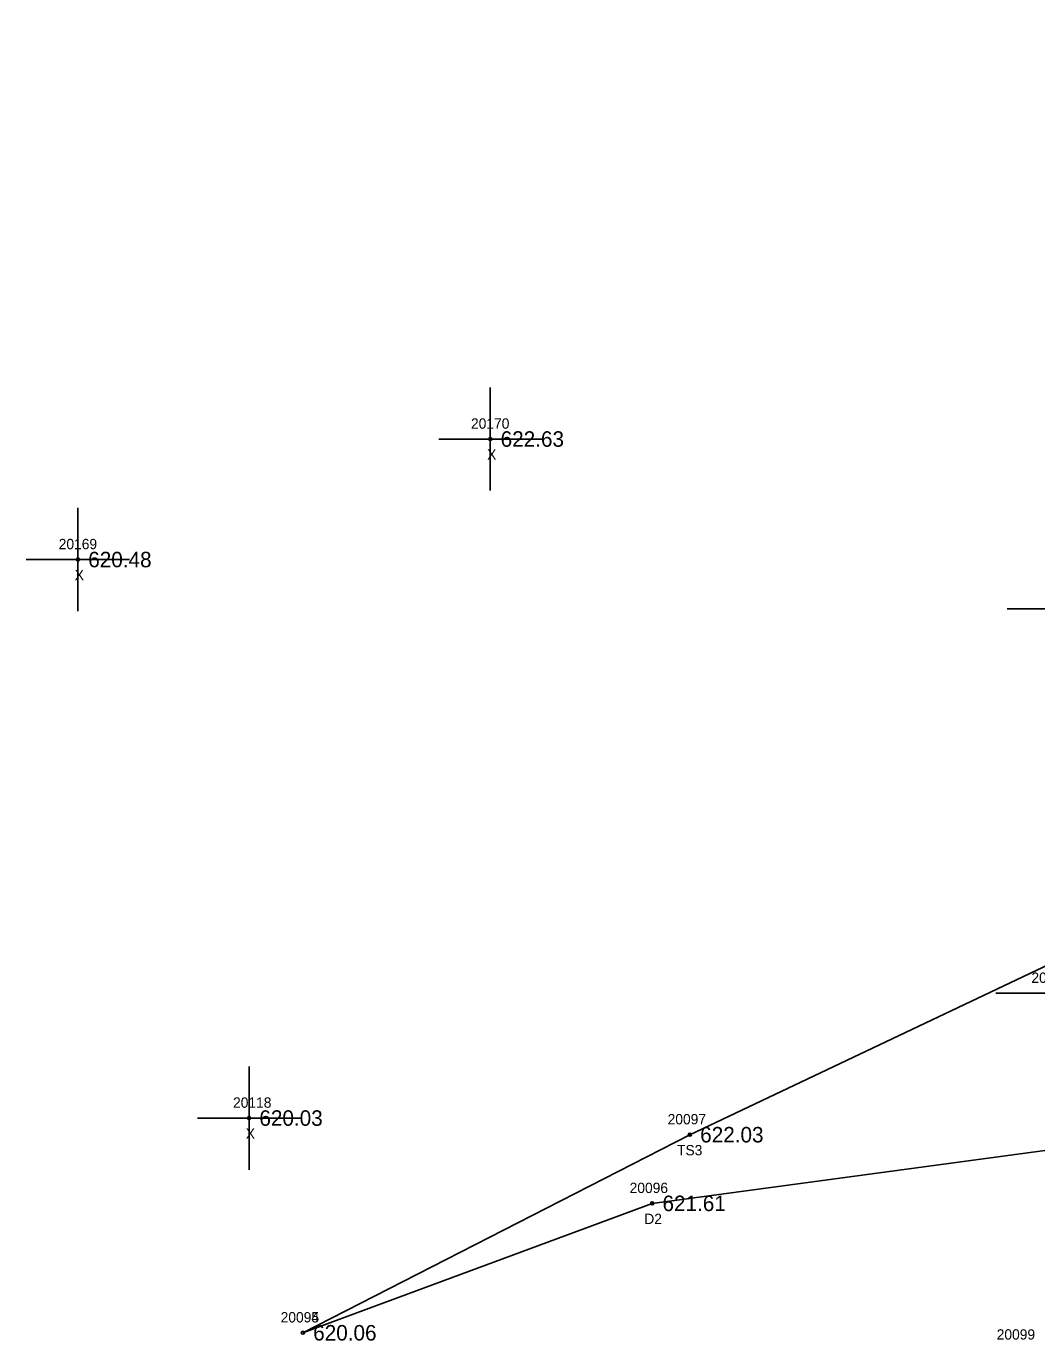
# Model space of a CAD drawing. Extents: x 1695443 to 1696344, y 1087542 to 1090645.
# Drawn here: x 1695784.6 to 1695882.4, y 1088055.7 to 1088182.9 of the extents above; entities that cross this region are included whole.
import ezdxf

# ---------------------------------------------------------------- set-up
doc = ezdxf.new("R2010")
doc.units = 0
for name, color, linetype in [('RD_DTM_BkLn2', 7, 'Continuous'), ('RD_DTM_BkLn_txCode', 7, 'Continuous'), ('RD_EX_Driveway', 7, 'Continuous'), ('RD_EX_Driveway_txCode', 7, 'Continuous'), ('RD_EX_Misc', 7, 'Continuous'), ('RD_EX_Misc_txCode', 7, 'Continuous'), ('RD_EX_TX_Driveway_ELEV', 7, 'Continuous'), ('RD_EX_TX_Misc_ELEV', 7, 'Continuous'), ('RD_SMD_Locator', 7, 'Continuous')]:
    doc.layers.add(name, color=color, linetype=linetype)

msp = doc.modelspace()

# ---------------------------------------------------------------- linework, layer by layer
at = {"layer": 'RD_DTM_BkLn2'}
msp.add_lwpolyline([(1695811.33, 1088056.44), (1695848.8, 1088075.62), (1695896.28, 1088098.14), (1695916.78, 1088084), (1695919.84, 1088133.52), (1695923.64, 1088187.73), (1695930.8, 1088232.96), (1695939.58, 1088289.44), (1695949.3, 1088339.9), (1695960.86, 1088397.31), (1695988.69, 1088500.86), (1696013.19, 1088605.35), (1696020.87, 1088659.75), (1696023.4, 1088706.14), (1696018.3, 1088755.38), (1696009.58, 1088802.31), (1695993.24, 1088846.7), (1695969.88, 1088894.03), (1695962.8, 1088910.68)], dxfattribs=at)
at = {"layer": 'RD_EX_Driveway'}
msp.add_lwpolyline([(1695811.33, 1088056.44), (1695845.15, 1088068.97), (1695920.27, 1088079.09)], dxfattribs=at)
at = {"layer": 'RD_EX_Misc'}
for p, q in [((1695829.48, 1088137.98), (1695829.48, 1088147.98)), ((1695824.48, 1088142.98), (1695834.48, 1088142.98)), ((1695789.55, 1088126.31), (1695789.55, 1088136.31)), ((1695784.55, 1088131.31), (1695794.55, 1088131.31)), ((1695879.53, 1088126.55), (1695889.53, 1088126.55)), ((1695878.43, 1088089.32), (1695888.43, 1088089.32)), ((1695806.12, 1088072.23), (1695806.12, 1088082.23)), ((1695801.12, 1088077.23), (1695811.12, 1088077.23))]:
    msp.add_line(p, q, dxfattribs=at)
at = {"layer": 'RD_SMD_Locator'}
for centre in [(1695829.48, 1088142.98), (1695789.55, 1088131.31), (1695806.12, 1088077.23), (1695848.8, 1088075.62), (1695845.15, 1088068.97), (1695811.33, 1088056.44), (1695811.33, 1088056.44)]:
    msp.add_circle(centre, 0.15, dxfattribs=at)

# ---------------------------------------------------------------- texts
at = {"layer": 'RD_DTM_BkLn_txCode'}
for s, p in [('20097', (1695846.65, 1088076.62)), ('TS3', (1695847.56, 1088073.62)), ('20094', (1695809.18, 1088057.44))]:
    msp.add_text(s, height=1, dxfattribs=at).set_placement(p)
at = {"layer": 'RD_EX_Driveway_txCode'}
for s, p in [('20096', (1695842.97, 1088069.97)), ('D2', (1695844.39, 1088066.97)), ('20095', (1695809.18, 1088057.44)), ('20099', (1695878.51, 1088055.78))]:
    msp.add_text(s, height=1, dxfattribs=at).set_placement(p)
at = {"layer": 'RD_EX_Misc_txCode'}
for s, p in [('20170', (1695827.61, 1088143.98)), ('X', (1695829.17, 1088140.98)), ('20169', (1695787.69, 1088132.31)), ('X', (1695789.24, 1088129.31)), ('20117', (1695881.87, 1088090.32)), ('20118', (1695804.57, 1088078.23)), ('X', (1695805.8, 1088075.23))]:
    msp.add_text(s, height=1, dxfattribs=at).set_placement(p)
at = {"layer": 'RD_EX_TX_Driveway_ELEV'}
for s, p in [('621.61', (1695846.15, 1088068.22)), ('620.06', (1695812.33, 1088055.69))]:
    msp.add_text(s, height=1.5, dxfattribs=at).set_placement(p)
at = {"layer": 'RD_EX_TX_Misc_ELEV'}
for s, p in [('622.63', (1695830.48, 1088142.23)), ('620.48', (1695790.55, 1088130.56)), ('620.03', (1695807.12, 1088076.48)), ('622.03', (1695849.8, 1088074.87)), ('620.06', (1695812.33, 1088055.69))]:
    msp.add_text(s, height=1.5, dxfattribs=at).set_placement(p)

doc.saveas('drawing.dxf')
